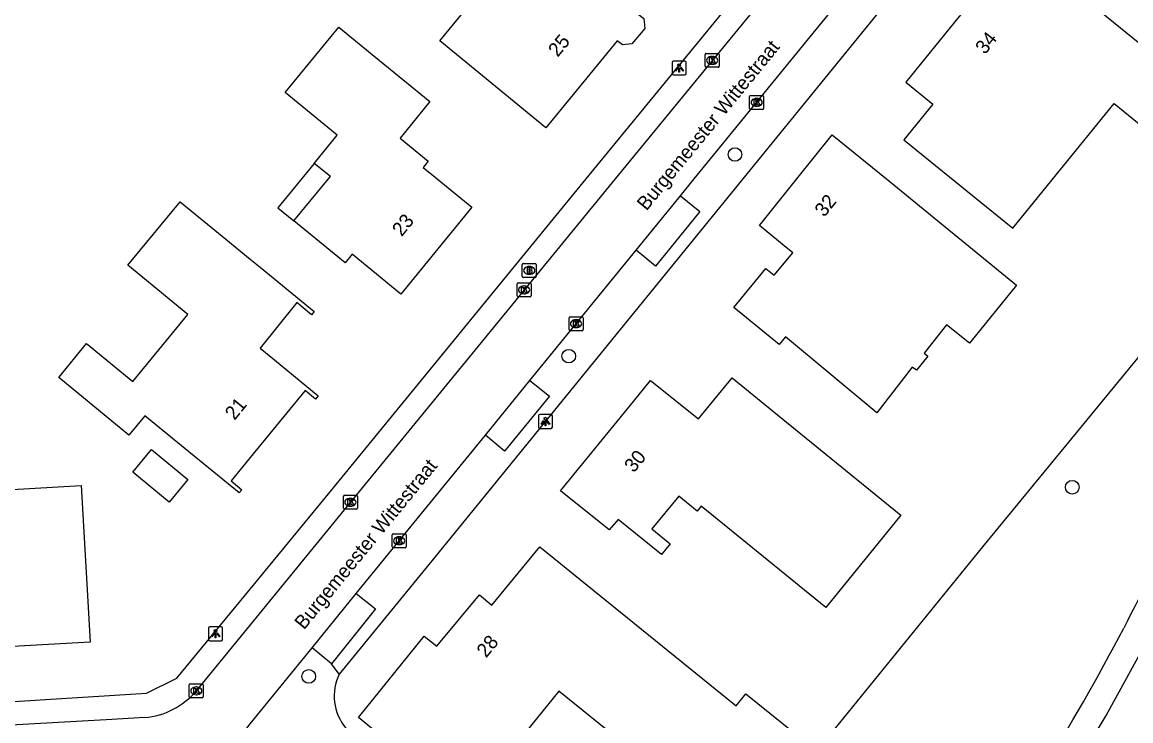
# Model space of a CAD drawing. Extents: x 159503 to 160347, y 382525 to 383272.
# Drawn here: x 159983.7 to 160063, y 382961.2 to 383011.2 of the extents above; entities that cross this region are included whole.
import ezdxf

# ---------------------------------------------------------------- set-up
doc = ezdxf.new("R2010")
doc.units = 0
for name, color, linetype in [('IMGEO_Boom', 7, 'Continuous'), ('IMGEO_Brandkraan', 7, 'Continuous'), ('IMGEO_Groenvoorziening', 7, 'Continuous'), ('IMGEO_Kolk', 7, 'Continuous'), ('IMGEO_Lichtpunt', 7, 'Continuous'), ('IMGEO_Openbare_ruimte_label', 7, 'Continuous'), ('IMGEO_Pand', 7, 'Continuous'), ('IMGEO_Pand_nummerreeks', 7, 'Continuous'), ('IMGEO_Pand_overbouw', 7, 'Continuous'), ('IMGEO_Rijbaan_lokaal_open', 7, 'Continuous'), ('IMGEO_Voetpad_halfverhard', 7, 'Continuous'), ('IMGEO_Voetpad_open', 7, 'Continuous')]:
    doc.layers.add(name, color=color, linetype=linetype)

msp = doc.modelspace()

# ---------------------------------------------------------------- linework, layer by layer
at = {"layer": 'IMGEO_Boom'}
for centre in [(160034.675, 383001.749), (160022.782, 382987.311), (160058.8, 382977.924), (160004.191, 382964.378)]:
    msp.add_circle(centre, 0.489, dxfattribs=at)
at = {"layer": 'IMGEO_Brandkraan'}
for p, q in [((160019.46, 382993.024), (160019.46, 382993.876)), ((160019.535, 382993.95), (160020.387, 382993.95)), ((160019.948, 382993.73), (160019.973, 382993.73)), ((160020.461, 382993.876), (160020.461, 382993.024)), ((160020.387, 382992.95), (160019.535, 382992.95)), ((160019.971, 382993.17), (160019.946, 382993.17))]:
    msp.add_line(p, q, dxfattribs=at)
for points in [[(160019.46, 382993.024), (160019.46, 382993.876)], [(160019.535, 382993.95), (160020.387, 382993.95)], [(160019.808, 382993.65), (160019.808, 382993.25), (160020.021, 382993.25)], [(160020.039, 382993.65), (160019.808, 382993.65)], [(160019.987, 382993.569), (160019.933, 382993.569), (160019.933, 382993.493)], [(160019.933, 382993.493), (160019.986, 382993.493)], [(160019.995, 382993.417), (160019.933, 382993.417), (160019.933, 382993.336)], [(160020.461, 382993.876), (160020.461, 382993.024)], [(160020.387, 382992.95), (160019.535, 382992.95)], [(160019.933, 382993.336), (160019.995, 382993.336)]]:
    msp.add_lwpolyline(points, dxfattribs=at)
for centre, radius, start, end in [((160019.537, 382993.874), 0.0765, 91.55205, 178.44795), ((160019.537, 382993.874), 0.0765, 91.55205, 178.44795), ((160019.988, 382993.531), 0.0379, 267.82845, 90.93552), ((160019.996, 382993.376), 0.0404, 269.87594, 90.50774), ((160020.043, 382993.505), 0.145, 59.4692, 91.53667), ((160020.068, 382993.552), 0.0922, 285.51372, 58.15012), ((160020.073, 382993.36), 0.105, 301.31148, 78.98903), ((160020.385, 382993.874), 0.0765, 1.55205, 88.44795), ((160020.385, 382993.874), 0.0765, 1.55205, 88.44795), ((160019.537, 382993.026), 0.0765, 181.55205, 268.44795), ((160019.537, 382993.026), 0.0765, 181.55205, 268.44795), ((160020.027, 382993.501), 0.251, 268.66757, 293.53466), ((160020.385, 382993.026), 0.0765, 271.55205, 358.44795), ((160020.385, 382993.026), 0.0765, 271.55205, 358.44795)]:
    msp.add_arc(centre, radius, start, end, dxfattribs=at)
for centre, major_axis, ratio, start_param, end_param in [((160019.947, 382993.45), (-0.387, 0.002), 0.722429, 4.712389, 7.853982), ((160019.972, 382993.45), (-0.39, 0.002), 0.717154, 1.570796, 4.712389)]:
    msp.add_ellipse(centre, major_axis=major_axis, ratio=ratio, start_param=start_param, end_param=end_param, dxfattribs=at)
at = {"layer": 'IMGEO_Groenvoorziening'}
msp.add_lwpolyline([(160031.009, 382947.305), (160052.413, 382973.653), (160074.019, 383000), (160086.515, 383015.238), (160064.154, 383036.884)], dxfattribs=at)
at = {"layer": 'IMGEO_Kolk'}
for p, q in [((160032.542, 383008.065), (160032.542, 383008.917)), ((160032.617, 383008.991), (160033.469, 383008.991)), ((160033.03, 383008.771), (160033.055, 383008.771)), ((160033.543, 383008.917), (160033.543, 383008.065)), ((160033.469, 383007.991), (160032.617, 383007.991)), ((160033.053, 383008.211), (160033.028, 383008.211)), ((160035.724, 383005.053), (160035.724, 383005.905)), ((160035.799, 383005.979), (160036.651, 383005.979)), ((160036.212, 383005.759), (160036.237, 383005.759)), ((160036.725, 383005.905), (160036.725, 383005.053)), ((160036.651, 383004.979), (160035.799, 383004.979)), ((160036.235, 383005.199), (160036.21, 383005.199)), ((160019.09, 382991.629), (160019.09, 382992.481)), ((160019.165, 382992.555), (160020.017, 382992.555)), ((160019.578, 382992.335), (160019.603, 382992.335)), ((160020.091, 382992.481), (160020.091, 382991.629)), ((160020.017, 382991.555), (160019.165, 382991.555)), ((160019.601, 382991.775), (160019.576, 382991.775)), ((160022.808, 382989.209), (160022.808, 382990.061)), ((160022.883, 382990.135), (160023.735, 382990.135)), ((160023.296, 382989.915), (160023.321, 382989.915)), ((160023.809, 382990.061), (160023.809, 382989.209)), ((160023.735, 382989.135), (160022.883, 382989.135)), ((160023.319, 382989.355), (160023.294, 382989.355)), ((160006.666, 382976.424), (160006.666, 382977.276)), ((160006.741, 382977.35), (160007.593, 382977.35)), ((160007.154, 382977.13), (160007.179, 382977.13)), ((160007.667, 382977.276), (160007.667, 382976.424)), ((160007.593, 382976.35), (160006.741, 382976.35)), ((160007.177, 382976.57), (160007.152, 382976.57)), ((160010.152, 382973.67), (160010.152, 382974.522)), ((160010.227, 382974.596), (160011.079, 382974.596)), ((160011.153, 382974.522), (160011.153, 382973.67)), ((160011.079, 382973.596), (160010.227, 382973.596)), ((160010.663, 382973.816), (160010.638, 382973.816)), ((160010.64, 382974.376), (160010.665, 382974.376)), ((159995.645, 382962.925), (159995.645, 382963.777)), ((159995.72, 382963.851), (159996.572, 382963.851)), ((159996.133, 382963.631), (159996.158, 382963.631)), ((159996.646, 382963.777), (159996.646, 382962.925)), ((159996.572, 382962.851), (159995.72, 382962.851)), ((159996.156, 382963.071), (159996.131, 382963.071))]:
    msp.add_line(p, q, dxfattribs=at)
for points in [[(160032.542, 383008.065), (160032.542, 383008.917)], [(160032.617, 383008.991), (160033.469, 383008.991)], [(160032.863, 383008.691), (160032.986, 383008.691), (160032.986, 383008.54), (160033.116, 383008.691), (160033.28, 383008.691), (160033.134, 383008.54), (160033.287, 383008.291), (160033.135, 383008.291), (160033.05, 383008.455), (160032.986, 383008.388), (160032.986, 383008.291), (160032.863, 383008.291), (160032.863, 383008.691)], [(160033.543, 383008.917), (160033.543, 383008.065)], [(160033.469, 383007.991), (160032.617, 383007.991)], [(160035.724, 383005.053), (160035.724, 383005.905)], [(160035.799, 383005.979), (160036.651, 383005.979)], [(160036.045, 383005.679), (160036.168, 383005.679), (160036.168, 383005.528), (160036.298, 383005.679), (160036.462, 383005.679), (160036.316, 383005.528), (160036.469, 383005.279), (160036.317, 383005.279), (160036.232, 383005.443), (160036.168, 383005.376), (160036.168, 383005.279), (160036.045, 383005.279), (160036.045, 383005.679)], [(160036.725, 383005.905), (160036.725, 383005.053)], [(160036.651, 383004.979), (160035.799, 383004.979)], [(160019.09, 382991.629), (160019.09, 382992.481)], [(160019.165, 382992.555), (160020.017, 382992.555)], [(160019.411, 382992.255), (160019.534, 382992.255), (160019.534, 382992.104), (160019.664, 382992.255), (160019.828, 382992.255), (160019.682, 382992.104), (160019.835, 382991.855), (160019.683, 382991.855), (160019.598, 382992.019), (160019.534, 382991.952), (160019.534, 382991.855), (160019.411, 382991.855), (160019.411, 382992.255)], [(160020.091, 382992.481), (160020.091, 382991.629)], [(160020.017, 382991.555), (160019.165, 382991.555)], [(160022.808, 382989.209), (160022.808, 382990.061)], [(160022.883, 382990.135), (160023.735, 382990.135)], [(160023.129, 382989.835), (160023.252, 382989.835), (160023.252, 382989.684), (160023.382, 382989.835), (160023.546, 382989.835), (160023.4, 382989.684), (160023.553, 382989.435), (160023.401, 382989.435), (160023.316, 382989.599), (160023.252, 382989.532), (160023.252, 382989.435), (160023.129, 382989.435), (160023.129, 382989.835)], [(160023.809, 382990.061), (160023.809, 382989.209)], [(160023.735, 382989.135), (160022.883, 382989.135)], [(160006.666, 382976.424), (160006.666, 382977.276)], [(160006.741, 382977.35), (160007.593, 382977.35)], [(160006.987, 382977.05), (160007.11, 382977.05), (160007.11, 382976.899), (160007.24, 382977.05), (160007.404, 382977.05), (160007.258, 382976.899), (160007.411, 382976.65), (160007.259, 382976.65), (160007.174, 382976.814), (160007.11, 382976.747), (160007.11, 382976.65), (160006.987, 382976.65), (160006.987, 382977.05)], [(160007.667, 382977.276), (160007.667, 382976.424)], [(160007.593, 382976.35), (160006.741, 382976.35)], [(160010.152, 382973.67), (160010.152, 382974.522)], [(160010.227, 382974.596), (160011.079, 382974.596)], [(160011.153, 382974.522), (160011.153, 382973.67)], [(160011.079, 382973.596), (160010.227, 382973.596)], [(160010.473, 382974.296), (160010.596, 382974.296), (160010.596, 382974.145), (160010.726, 382974.296), (160010.89, 382974.296), (160010.744, 382974.145), (160010.897, 382973.896), (160010.745, 382973.896), (160010.66, 382974.06), (160010.596, 382973.993), (160010.596, 382973.896), (160010.473, 382973.896), (160010.473, 382974.296)], [(159995.645, 382962.925), (159995.645, 382963.777)], [(159995.72, 382963.851), (159996.572, 382963.851)], [(159995.966, 382963.551), (159996.089, 382963.551), (159996.089, 382963.4), (159996.219, 382963.551), (159996.383, 382963.551), (159996.237, 382963.4), (159996.39, 382963.151), (159996.238, 382963.151), (159996.153, 382963.315), (159996.089, 382963.248), (159996.089, 382963.151), (159995.966, 382963.151), (159995.966, 382963.551)], [(159996.646, 382963.777), (159996.646, 382962.925)], [(159996.572, 382962.851), (159995.72, 382962.851)]]:
    msp.add_lwpolyline(points, dxfattribs=at)
for centre, start, end in [((160032.619, 383008.915), 91.55205, 178.44795), ((160032.619, 383008.915), 91.55205, 178.44795), ((160033.467, 383008.915), 1.55205, 88.44795), ((160033.467, 383008.915), 1.55205, 88.44795), ((160032.619, 383008.067), 181.55205, 268.44795), ((160032.619, 383008.067), 181.55205, 268.44795), ((160033.467, 383008.067), 271.55205, 358.44795), ((160033.467, 383008.067), 271.55205, 358.44795), ((160035.801, 383005.903), 91.55205, 178.44795), ((160035.801, 383005.903), 91.55205, 178.44795), ((160036.649, 383005.903), 1.55205, 88.44795), ((160036.649, 383005.903), 1.55205, 88.44795), ((160035.801, 383005.055), 181.55205, 268.44795), ((160035.801, 383005.055), 181.55205, 268.44795), ((160036.649, 383005.055), 271.55205, 358.44795), ((160036.649, 383005.055), 271.55205, 358.44795), ((160019.167, 382992.479), 91.55205, 178.44795), ((160019.167, 382992.479), 91.55205, 178.44795), ((160020.015, 382992.479), 1.55205, 88.44795), ((160020.015, 382992.479), 1.55205, 88.44795), ((160019.167, 382991.631), 181.55205, 268.44795), ((160019.167, 382991.631), 181.55205, 268.44795), ((160020.015, 382991.631), 271.55205, 358.44795), ((160020.015, 382991.631), 271.55205, 358.44795), ((160022.885, 382990.059), 91.55205, 178.44795), ((160022.885, 382990.059), 91.55205, 178.44795), ((160023.733, 382990.059), 1.55205, 88.44795), ((160023.733, 382990.059), 1.55205, 88.44795), ((160022.885, 382989.211), 181.55205, 268.44795), ((160022.885, 382989.211), 181.55205, 268.44795), ((160023.733, 382989.211), 271.55205, 358.44795), ((160023.733, 382989.211), 271.55205, 358.44795), ((160006.743, 382977.274), 91.55205, 178.44795), ((160006.743, 382977.274), 91.55205, 178.44795), ((160007.591, 382977.274), 1.55205, 88.44795), ((160007.591, 382977.274), 1.55205, 88.44795), ((160006.743, 382976.426), 181.55205, 268.44795), ((160006.743, 382976.426), 181.55205, 268.44795), ((160007.591, 382976.426), 271.55205, 358.44795), ((160007.591, 382976.426), 271.55205, 358.44795), ((160010.229, 382974.52), 91.55205, 178.44795), ((160010.229, 382974.52), 91.55205, 178.44795), ((160011.077, 382974.52), 1.55205, 88.44795), ((160011.077, 382974.52), 1.55205, 88.44795), ((160010.229, 382973.672), 181.55205, 268.44795), ((160010.229, 382973.672), 181.55205, 268.44795), ((160011.077, 382973.672), 271.55205, 358.44795), ((160011.077, 382973.672), 271.55205, 358.44795), ((159995.722, 382963.775), 91.55205, 178.44795), ((159995.722, 382963.775), 91.55205, 178.44795), ((159996.57, 382963.775), 1.55205, 88.44795), ((159996.57, 382963.775), 1.55205, 88.44795), ((159995.722, 382962.927), 181.55205, 268.44795), ((159995.722, 382962.927), 181.55205, 268.44795), ((159996.57, 382962.927), 271.55205, 358.44795), ((159996.57, 382962.927), 271.55205, 358.44795)]:
    msp.add_arc(centre, 0.0765, start, end, dxfattribs=at)
for centre, major_axis, ratio, start_param, end_param in [((160033.029, 383008.491), (-0.387, 0.002), 0.722429, 4.712389, 7.853982), ((160033.054, 383008.491), (-0.39, 0.002), 0.717154, 1.570796, 4.712389), ((160036.211, 383005.479), (-0.387, 0.002), 0.722429, 4.712389, 7.853982), ((160036.236, 383005.479), (-0.39, 0.002), 0.717154, 1.570796, 4.712389), ((160019.577, 382992.055), (-0.387, 0.002), 0.722429, 4.712389, 7.853982), ((160019.602, 382992.055), (-0.39, 0.002), 0.717154, 1.570796, 4.712389), ((160023.295, 382989.635), (-0.387, 0.002), 0.722429, 4.712389, 7.853982), ((160023.32, 382989.635), (-0.39, 0.002), 0.717154, 1.570796, 4.712389), ((160007.153, 382976.85), (-0.387, 0.002), 0.722429, 4.712389, 7.853982), ((160007.178, 382976.85), (-0.39, 0.002), 0.717154, 1.570796, 4.712389), ((160010.639, 382974.096), (-0.387, 0.002), 0.722429, 4.712389, 7.853982), ((160010.664, 382974.096), (-0.39, 0.002), 0.717154, 1.570796, 4.712389), ((159996.132, 382963.351), (-0.387, 0.002), 0.722429, 4.712389, 7.853982), ((159996.157, 382963.351), (-0.39, 0.002), 0.717154, 1.570796, 4.712389)]:
    msp.add_ellipse(centre, major_axis=major_axis, ratio=ratio, start_param=start_param, end_param=end_param, dxfattribs=at)
at = {"layer": 'IMGEO_Lichtpunt'}
for p, q in [((160030.188, 383008.343), (160030.188, 383007.536)), ((160030.188, 383008.343), (160030.188, 383007.536)), ((160031.09, 383008.438), (160030.282, 383008.438)), ((160031.09, 383008.438), (160030.282, 383008.438)), ((160031.184, 383007.536), (160031.184, 383008.343)), ((160031.184, 383007.536), (160031.184, 383008.343)), ((160030.282, 383007.442), (160031.09, 383007.442)), ((160030.282, 383007.442), (160031.09, 383007.442)), ((160021.517, 382983.133), (160020.709, 382983.133)), ((160021.517, 382983.133), (160020.709, 382983.133)), ((160020.615, 382983.038), (160020.615, 382982.231)), ((160020.615, 382983.038), (160020.615, 382982.231)), ((160021.611, 382982.231), (160021.611, 382983.038)), ((160021.611, 382982.231), (160021.611, 382983.038)), ((160020.709, 382982.137), (160021.517, 382982.137)), ((160020.709, 382982.137), (160021.517, 382982.137)), ((159997.024, 382967.84), (159997.024, 382967.033)), ((159997.024, 382967.84), (159997.024, 382967.033)), ((159997.926, 382967.935), (159997.118, 382967.935)), ((159997.926, 382967.935), (159997.118, 382967.935)), ((159998.02, 382967.033), (159998.02, 382967.84)), ((159998.02, 382967.033), (159998.02, 382967.84)), ((159997.118, 382966.939), (159997.926, 382966.939)), ((159997.118, 382966.939), (159997.926, 382966.939))]:
    msp.add_line(p, q, dxfattribs=at)
for points in [[(160030.562, 383008.007), (160030.601, 383007.979), (160030.413, 383007.717), (160030.375, 383007.744), (160030.562, 383008.007)], [(160030.664, 383007.959), (160030.711, 383007.959), (160030.711, 383007.637), (160030.664, 383007.637), (160030.664, 383007.959)], [(160030.774, 383007.979), (160030.812, 383008.006), (160030.999, 383007.744), (160030.96, 383007.716), (160030.774, 383007.979)], [(160020.989, 382982.702), (160021.028, 382982.674), (160020.84, 382982.412), (160020.802, 382982.439), (160020.989, 382982.702)], [(160021.091, 382982.654), (160021.138, 382982.654), (160021.138, 382982.332), (160021.091, 382982.332), (160021.091, 382982.654)], [(160021.201, 382982.674), (160021.239, 382982.701), (160021.426, 382982.439), (160021.387, 382982.411), (160021.201, 382982.674)], [(159997.398, 382967.504), (159997.437, 382967.476), (159997.249, 382967.214), (159997.211, 382967.241), (159997.398, 382967.504)], [(159997.5, 382967.456), (159997.547, 382967.456), (159997.547, 382967.134), (159997.5, 382967.134), (159997.5, 382967.456)], [(159997.61, 382967.476), (159997.648, 382967.503), (159997.835, 382967.241), (159997.796, 382967.213), (159997.61, 382967.476)]]:
    msp.add_lwpolyline(points, dxfattribs=at)
for centre in [(160030.687, 383008.141), (160021.114, 382982.836), (159997.523, 382967.638)]:
    msp.add_circle(centre, 0.0994, dxfattribs=at)
for centre, start, end in [((160030.282, 383008.343), 90, 180), ((160030.282, 383008.343), 90, 180), ((160031.09, 383008.343), 0, 90), ((160031.09, 383008.343), 0, 90), ((160030.282, 383007.536), 180, 270), ((160030.282, 383007.536), 180, 270), ((160031.09, 383007.536), 270, 0), ((160031.09, 383007.536), 270, 360), ((160020.709, 382983.038), 90, 180), ((160020.709, 382983.038), 90, 180), ((160021.517, 382983.038), 0, 90), ((160021.517, 382983.038), 0, 90), ((160020.709, 382982.231), 180, 270), ((160020.709, 382982.231), 180, 270), ((160021.517, 382982.231), 270, 0), ((160021.517, 382982.231), 270, 360), ((159997.118, 382967.84), 90, 180), ((159997.118, 382967.84), 90, 180), ((159997.926, 382967.84), 0, 90), ((159997.926, 382967.84), 0, 90), ((159997.118, 382967.033), 180, 270), ((159997.118, 382967.033), 180, 270), ((159997.926, 382967.033), 270, 0), ((159997.926, 382967.033), 270, 360)]:
    msp.add_arc(centre, 0.0946, start, end, dxfattribs=at)
at = {"layer": 'IMGEO_Pand'}
for points in [[(160028.12, 383017.82), (160028.927, 383017.161), (160026.624, 383014.376), (160026.663, 383014.101), (160026.82, 383012.513), (160028.146, 383011.474), (160028.232, 383010.766), (160027.306, 383009.661), (160026.619, 383009.6), (160026.258, 383009.888), (160021.143, 383003.663), (160017.28, 383006.838), (160013.564, 383009.891), (160017.577, 383014.775), (160017.364, 383016.942), (160018.837, 383018.735), (160021.015, 383018.927), (160023.316, 383021.728)], [(160061.789, 383005.395), (160067.586, 383000.685), (160070.418, 383004.169), (160058.099, 383014.178), (160057.47, 383013.403), (160052.972, 383017.056), (160050.659, 383014.209), (160051.945, 383013.165), (160050.367, 383011.221), (160046.885, 383006.933), (160048.832, 383005.352), (160046.754, 383002.794), (160054.54, 382996.47), (160061.789, 383005.395)], [(160006.346, 383010.863), (160008.984, 383008.702), (160012.851, 383005.533), (160010.72, 383002.916), (160012.733, 383001.277), (160012.373, 383000.812), (160013.219, 383000.124), (160013.371, 383000), (160015.849, 382997.985), (160010.776, 382991.756), (160007.292, 382994.612), (160006.785, 382993.992), (160003.13, 382996.989), (160005.599, 383000), (160005.733, 383000.164), (160004.572, 383001.116), (160006.222, 383003.131), (160002.507, 383006.178), (160006.346, 383010.863)], [(160034.602, 382990.807), (160036.885, 382993.599), (160037.483, 382993.104), (160038.802, 382994.704), (160038.198, 382995.204), (160036.42, 382996.676), (160039.09, 383000), (160041.631, 383003.164), (160045.507, 383000), (160054.82, 382992.397), (160051.441, 382988.25), (160049.799, 382989.545), (160048.212, 382987.537), (160048.471, 382987.314), (160047.657, 382986.319), (160047.349, 382986.525), (160044.81, 382983.264), (160038.291, 382988.69), (160037.833, 382988.148), (160034.602, 382990.807)], [(159988.303, 382988.208), (159991.605, 382985.499), (159995.547, 382990.302), (159991.259, 382993.822), (159994.989, 382998.368), (159998.247, 382995.694), (160000, 382994.256), (160000.702, 382993.68), (160004.567, 382990.508), (160004.377, 382990.277), (160003.327, 382991.149), (160000.703, 382987.888), (160001.735, 382987.044), (160004.866, 382984.483), (160004.681, 382984.243), (160003.922, 382984.861), (160000, 382980.058), (159998.643, 382978.396), (159999.406, 382977.748), (159999.206, 382977.516), (159995.341, 382980.688), (159992.465, 382983.047), (159991.323, 382981.656), (159986.305, 382985.773), (159988.303, 382988.208)], [(160030.648, 382977.285), (160028.731, 382974.948), (160030.042, 382973.872), (160029.408, 382973.1), (160026.322, 382975.62), (160025.668, 382974.868), (160022.198, 382977.675), (160027.413, 382984.066), (160028.644, 382985.575), (160032.069, 382982.833), (160034.475, 382985.754), (160038.352, 382982.597), (160046.532, 382975.935), (160041.167, 382969.32), (160032.251, 382976.566), (160031.96, 382976.211), (160030.648, 382977.285)], [(159987.908, 382978.054), (159988.265, 382971.829), (159988.551, 382966.837), (159982.16, 382966.482), (159982.117, 382967.02), (159980.216, 382966.903), (159980.265, 382966.415), (159974.571, 382966.048), (159974.248, 382971.235), (159971.787, 382971.11), (159969.948, 382972.492), (159968.113, 382970.035), (159962.862, 382974.012), (159965.887, 382977.994), (159967.689, 382980.367), (159972.945, 382976.375), (159973.964, 382976.433), (159973.916, 382977.252), (159987.908, 382978.054)], [(159995.535, 382978.492), (159994.204, 382976.87), (159991.603, 382979.004), (159992.933, 382980.626), (159995.535, 382978.492)], [(160011.78, 382954.169), (160012.771, 382955.393), (160011.986, 382956.029), (160012.916, 382957.191), (160007.749, 382961.454), (160012.437, 382967.265), (160013.346, 382966.541), (160016.393, 382970.234), (160017.292, 382969.479), (160020.71, 382973.659), (160024.597, 382970.514), (160034.771, 382962.282), (160035.463, 382963.138), (160039.738, 382959.678), (160032.064, 382950.194), (160028.799, 382952.836), (160029.96, 382954.246), (160031.282, 382955.879), (160022.074, 382963.331), (160017.918, 382958.195), (160018.929, 382957.378), (160015.521, 382953.167), (160015.375, 382953.286), (160014.004, 382951.592)]]:
    msp.add_lwpolyline(points, dxfattribs=at)
at = {"layer": 'IMGEO_Pand_overbouw'}
msp.add_lwpolyline([(160005.599, 383000), (160005.733, 383000.164), (160004.572, 383001.116), (160001.971, 382997.94), (160003.13, 382996.989)], close=True, dxfattribs=at)
at = {"layer": 'IMGEO_Rijbaan_lokaal_open'}
for points in [[(160056.791, 383026.642), (160055.985, 383025.521), (160035.23, 383000), (160013.21, 382972.924), (160006.361, 382964.545)], [(160037.807, 383014.31), (160026.095, 383000), (160007.147, 382976.842), (160000, 382968.07), (159996.142, 382963.344)], [(160030.786, 382998.795), (160031.767, 383000), (160042.078, 383012.654)], [(160027.604, 382994.891), (160030.786, 382998.795)], [(160030.786, 382998.795), (160032.171, 382997.658), (160028.981, 382993.743), (160027.604, 382994.891)], [(160020, 382985.559), (160027.604, 382994.891)], [(160016.821, 382981.656), (160020, 382985.559)], [(160020, 382985.559), (160021.402, 382984.443), (160018.2, 382980.518), (160016.821, 382981.656)], [(160007.59, 382970.326), (160016.821, 382981.656)], [(160004.421, 382966.424), (160007.59, 382970.326)], [(160007.59, 382970.326), (160008.954, 382969.217), (160005.808, 382965.295)], [(159999.59, 382960.475), (160000, 382960.98), (160004.421, 382966.424)], [(160005.808, 382965.295), (160004.421, 382966.424)], [(160006.361, 382964.545), (160005.808, 382965.295)], [(159992.466, 382961.44), (159989.696, 382961.282), (159982.453, 382960.859)]]:
    msp.add_lwpolyline(points, dxfattribs=at)
for centre, radius, start, end in [((160009.628, 382962.985), 3.62, 154.47332, 219.36689), ((159991.996, 382966.848), 5.428, 274.96674, 319.79745)]:
    msp.add_arc(centre, radius, start, end, dxfattribs=at)
at = {"layer": 'IMGEO_Voetpad_halfverhard'}
msp.add_lwpolyline([(160039.892, 382932.533), (160052.089, 382948.183), (160055.15, 382952.189), (160058.065, 382956.302), (160061.224, 382961.584), (160064.191, 382966.975)], dxfattribs=at)
for centre, radius, start, end in [((160302.222, 382846.082), 268.891, 149.00181, 153.07533), ((159940.98, 383030.78), 136.832, 327.57772, 332.61456)]:
    msp.add_arc(centre, radius, start, end, dxfattribs=at)
at = {"layer": 'IMGEO_Voetpad_open'}
msp.add_lwpolyline([(159982.324, 382962.546), (159992.571, 382963.192), (159994.756, 382964.255), (160000, 382970.621), (160005.936, 382977.853), (160024.041, 383000), (160036.566, 383015.316)], dxfattribs=at)

# ---------------------------------------------------------------- texts
at = {"layer": 'IMGEO_Openbare_ruimte_label'}
for p in [(160028.347, 382997.67), (160003.855, 382967.675)]:
    msp.add_text('Burgemeester Wittestraat', height=1, rotation=50.80331, dxfattribs=at).set_placement(p)
at = {"layer": 'IMGEO_Pand_nummerreeks'}
for s, rotation, p in [('25', 50.59217, (160021.994, 383008.67)), ('34', 51.88706, (160052.565, 383008.86)), ('32', 51.22944, (160041.064, 382997.219)), ('23', 50.84006, (160010.837, 382995.822)), ('21', 50.76662, (159998.879, 382982.67)), ('30', 50.7873, (160027.441, 382978.914)), ('28', 50.47483, (160016.877, 382965.667))]:
    msp.add_text(s, height=1, rotation=rotation, dxfattribs=at).set_placement(p)

doc.saveas('drawing.dxf')
